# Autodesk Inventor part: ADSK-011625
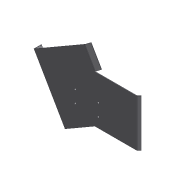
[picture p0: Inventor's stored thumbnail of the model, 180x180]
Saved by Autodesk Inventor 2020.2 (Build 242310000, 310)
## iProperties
Created: 2000-02
Part Number: ADSK-011625
Description: FSHTPH,SS,CP,01,204,165,016,LONG SIDE PAN
Document SubType Name: Tôlerie
Designer: sspink
Material: 1.0312 DC05
Density: 1 g/cm^3
Sheet Metal Rule: Stahlblech 1.0312 - DC05 -   3.0 mm
Appearance: Metal-Steel(Polish)
Mass: 416.174 g
Surface Area: 2829.69 cm^2
Volume: 416.174 cm^3
Flat Pattern Width: 41.2711 cm
Flat Pattern Length: 51.1016 cm
Flat Pattern Area: 2109.02 cm^2
Sheet Metal Width: 412,711 mm
Sheet Metal Length: 511,016 mm
Sheet Metal Area: 210902,122 mm^2
Control State: 0
Master: False
Checked Out: False
Shininess: 57.0
Length Units: 11269
Angle Units: 11279
Time Units: 11290
Mass Units: 11283
Length Display Precision: 3
Angle Display Precision: 2
Compacted: True
Cutlength: 17.31 X 21.83  (378 SI)
Material Desc: SHEET,S/S,11 GAUGE,#2B
Material_Number: A084638
G_L: 412,7x511 mm
Thickness: 3,000 mm
Dimensions: 418,4x38x517,8 mm
Mass: 0,416 kg
Semi finished: Stahlblech 1.0312 - DC05 -   3.0 mm
VLT_Material: 1.0312 DC05
Density: 8.03
Volumn: 445.9318843789838
Area: 2866.578471941876
PropertySet Name: Model Information
Author: sspink
Revision Number: -
Title: FSHTPH,SS,CP,01,204,165,016,LONG SIDE PAN
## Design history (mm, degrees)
node "Face1"
  sketch "Sketch1"
    geometry: L1 (0, 0)-(405, 0); L2 (405, 0)-(405, 230); L3 (405, 230)-(0, 230); L4 (0, 230)-(0, 0); L5 (0, 0)-(-101.5, 175.803); L6 (-101.5, 175.803)-(149.968, 320.988); L7 (149.968, 320.988)-(202.5, 230); L8 (0, 0)-(50, -86.603); L9 (50, -86.603)-(200, 0)
    constraints: 18 end point, 4 perpendicular, 2 parallel, 2 point on line, 1 horizontal, 1 midpoint
    dimensions: "d0" = 230 distance between parallel lines of L3 L1; "d1" = 405 distance between parallel lines of L2 L4; "d3" = 60 deg angle of L7 L3; "d4" = 203 distance of L1.start L5.end; "d14" = 100 distance of L1.start L8.end
node "Hole2" dims "d30" = 9, "d31" = 9.525, "d32" = 6.35, "d33" = 60 deg, "d34" = 19.05, "d35" = 118 deg, "d80" = 6
  sketch "Sketch6"
    geometry: L1 (0, -230)-(0, 0) reference; L2 (205, -230)-(0, -230) reference; 4 further points
    constraints: 2 horizontal alignment, 2 vertical alignment
    dimensions: "d25" = 47.5 distance from line of point (188, -182.5) L2; "d27" = 188 distance from line of point (188, -182.5) L1; "d29" = 114 distance of point (302, -122.5) point (188, -122.5); "d36" = 60 distance of point (188, -122.5) point (188, -182.5)
node "Lasche5"
node "Lasche6"
node "Lasche7"
sketch "Skizze11"
  geometry: L1 (16, -67.5)-(16, -92.5); L2 (16, -157.5)-(16, -182.5); L3 (0, -303)-(0, 0) reference; L4 (0, 0)-(32, 0) reference; 1 further point
  constraints: 4 end point, 2 vertical, 1 collinear
  dimensions: "d81" = 25 distance of L1.start L1.end; "d82" = 25 distance of L2.start L2.end (= d81); "d83" = 16 distance between parallel lines of L3 L1; "d84" = 67.5 distance from line of L4 L1.start; "d85" = 65 distance of L2.start L1.end
hole "Bohrung3" sketch "Skizze11" at (16, -67.5), (16, -92.5), (16, -157.5), (16, -182.5) diameter "d86" = 5.5; stored, may be unused: countersink angle "d90" = 90 deg, drill point angle "d92" = 118 deg; dims "d87" = 6, "d88" = 10.4, "d89" = 2, "d91" = 3 (= Thickness)
node "Solide1"
node "Corps solides"
node "Corps surfaciques"
node "Plate1" dims "d49" = 3 (= Thickness)
sketch "Skizze8"
  geometry: L1 (105.064, 0)-(3, 0); L2 (3, 0)-(3, -25); L3 (3, -25)-(105.064, -25); L4 (105.064, -25)-(105.064, 0)
  constraints: 8 end point
feature "Grobblech6" dims "d49" = 3 (= Thickness), "d50" = 3 (= BendReliefWidth), "d51" = 1.5 (= BendReliefDepth), "d52" = 6 (= MinimumRemnant), "d53" = 3 (= TransitionRadius), "d54" = 25, "d55" = 30 deg, "d56" = 3 (= BendRadius), "d57" = 12 (= CornerReliefSize), "d58" = 3 (= TailleJeu), "d59" = 3 (= TailleRayonJacobi), "SeamGap" = 0.00508
feature "Biegung5" dims "d49" = 3 (= Thickness), "d50" = 3 (= BendReliefWidth), "d51" = 1.5 (= BendReliefDepth), "d52" = 6 (= MinimumRemnant), "d53" = 3 (= TransitionRadius), "d54" = 25, "d55" = 30 deg, "d56" = 3 (= BendRadius), "SeamGap" = 0.00508
feature "Ecke1" dims "d54" = 25, "d55" = 30 deg, "d57" = 12 (= CornerReliefSize), "d58" = 3 (= TailleJeu), "d59" = 3 (= TailleRayonJacobi)
sketch "Skizze9"
  geometry: L1 through (151.5, 0) direction (-1, 6.51e-33); L2 through (0, -19) direction (0, -1); L3 (0, -38)-(303, -38); L4 (303, -38)-(303, 0)
  constraints: 6 end point, 1 horizontal, 1 perpendicular, 1 vertical
feature "Grobblech7" dims "d49" = 3 (= Thickness), "d60" = 3 (= BendReliefWidth), "d61" = 1.5 (= BendReliefDepth), "d62" = 6 (= MinimumRemnant), "d63" = 3 (= TransitionRadius), "d64" = 38, "d65" = 90 deg, "d66" = 3 (= BendRadius), "d67" = 12 (= CornerReliefSize), "d68" = 3 (= TailleJeu), "d69" = 3 (= TailleRayonJacobi), "SeamGap" = 0.00508
feature "Biegung6" dims "d49" = 3 (= Thickness), "d60" = 3 (= BendReliefWidth), "d61" = 1.5 (= BendReliefDepth), "d62" = 6 (= MinimumRemnant), "d63" = 3 (= TransitionRadius), "d64" = 38, "d65" = 90 deg, "d66" = 3 (= BendRadius), "SeamGap" = 0.00508
feature "Ecke2" dims "d64" = 38, "d65" = 90 deg, "d67" = 12 (= CornerReliefSize), "d68" = 3 (= TailleJeu), "d69" = 3 (= TailleRayonJacobi)
sketch "Skizze10"
  geometry: L1 through (115, 0) direction (-1, 0); L2 through (0, -8) direction (4.93e-31, -1); L3 (0, -16)-(230, -16); L4 (230, -16)-(230, 0)
  constraints: 6 end point, 1 horizontal, 1 perpendicular, 1 vertical
feature "Grobblech8" dims "d49" = 3 (= Thickness), "d70" = 3 (= BendReliefWidth), "d71" = 1.5 (= BendReliefDepth), "d72" = 6 (= MinimumRemnant), "d73" = 3 (= TransitionRadius), "d74" = 16, "d75" = 45 deg, "d76" = 3 (= BendRadius), "d77" = 12 (= CornerReliefSize), "d78" = 3 (= TailleJeu), "d79" = 3 (= TailleRayonJacobi), "SeamGap" = 0.00508
feature "Biegung7" dims "d49" = 3 (= Thickness), "d70" = 3 (= BendReliefWidth), "d71" = 1.5 (= BendReliefDepth), "d72" = 6 (= MinimumRemnant), "d73" = 3 (= TransitionRadius), "d74" = 16, "d75" = 45 deg, "d76" = 3 (= BendRadius), "SeamGap" = 0.00508
feature "Ecke3" dims "d74" = 16, "d75" = 45 deg, "d77" = 12 (= CornerReliefSize), "d78" = 3 (= TailleJeu), "d79" = 3 (= TailleRayonJacobi)
feature "Definition1"
other parameters: "Thickness" = 3 (derived), "BendRadius" = 3 (= Thickness), "BendReliefWidth" = 3 (= Thickness), "BendReliefDepth" = 1.5 (= 0.5 x Thickness), "CornerReliefSize" = 12 (= 4 x Thickness), "MinimumRemnant" = 6 (= 2 x Thickness), "d2" = 3 (= BendRadius), "d37" = 15.875, "d38" = 45 deg, "d39" = 3 (= BendRadius), "TransitionRadius" = 3 (= BendRadius), "TailleRayonJacobi" = 3 (= BendRadius), "TailleJeu" = 3 (= Thickness), "BendRadius" = 3, "BendReliefDepth" = 1.5, "BendReliefWidth" = 3, "CornerReliefSize" = 12, "MinimumRemnant" = 6, "TailleJeu" = 3, "TailleRayonJacobi" = 3, "Thickness" = 3, "TransitionRadius" = 3
